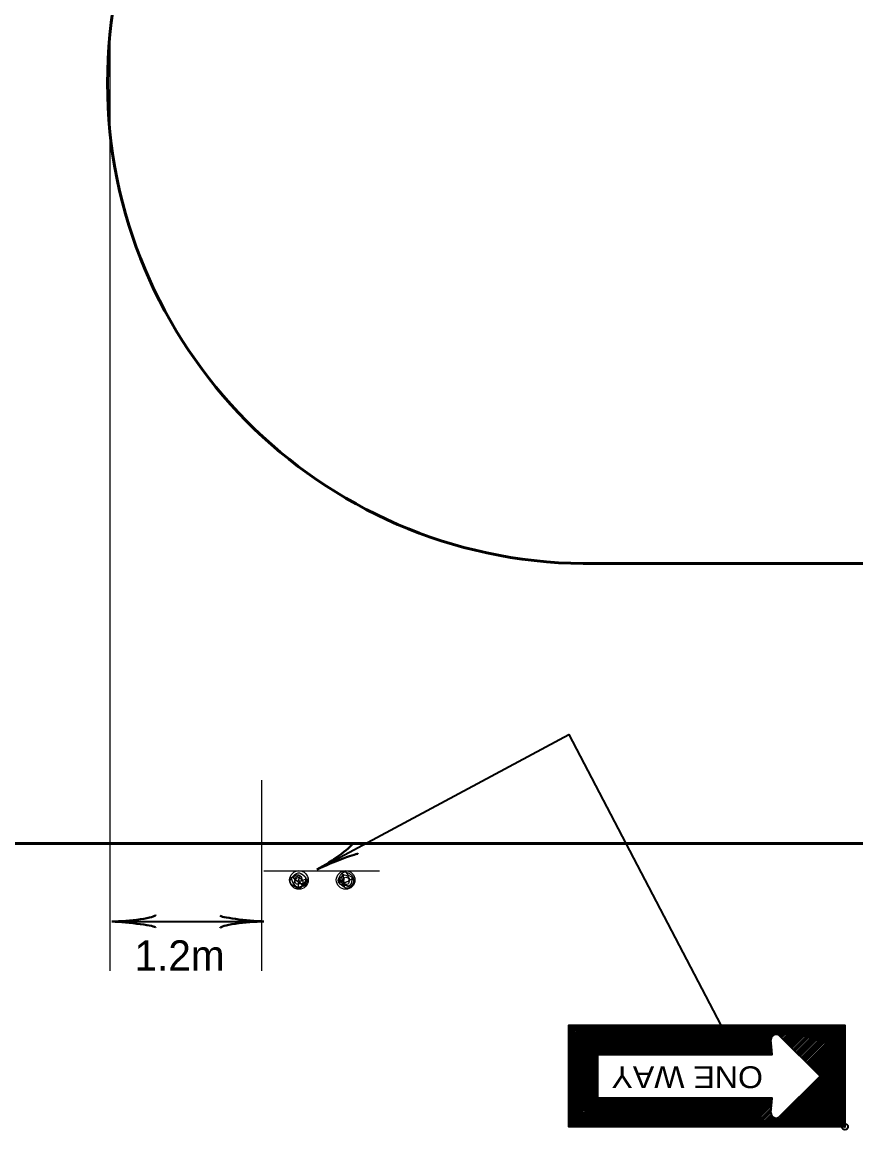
# Model space of a CAD drawing. Extents: x -198 to 658, y -402 to 142.
# Drawn here: x 64.2 to 130.3, y -164.9 to -77.1 of the extents above; entities that cross this region are included whole.
import ezdxf
from ezdxf.enums import TextEntityAlignment as Align

# ---------------------------------------------------------------- set-up
doc = ezdxf.new("R2010")
doc.units = 0
doc.header["$LTSCALE"] = 0.96
doc.header["$PDMODE"] = 32
doc.header["$PDSIZE"] = 0.48
doc.layers.add('1', color=7, linetype='Continuous', lineweight=35)
doc.layers.add('4', color=7, linetype='Continuous', lineweight=25)

msp = doc.modelspace()

# ---------------------------------------------------------------- linework, layer by layer
at = {"layer": '1', "lineweight": 25}
for p, q in [((71.1619, -152.3203), (71.1619, -77.8663)), ((83.1828, -152.3203), (83.1828, -137.1946)), ((92.5121, -144.4125), (83.3321, -144.4125))]:
    msp.add_line(p, q, dxfattribs=at)
at = {"layer": '1', "lineweight": 53}
for p, q in [((234.6408, -120.0238), (108.6408, -120.0238)), ((-105.2517, -142.2238), (234.6408, -142.2238))]:
    msp.add_line(p, q, dxfattribs=at)
at = {"layer": '1'}
for p, q in [((71.3032, -148.4168), (83.3241, -148.4168)), ((112.0494, -156.6375), (107.5134, -161.1735)), ((111.8814, -156.6375), (107.5134, -161.0055)), ((111.7134, -156.6375), (107.5134, -160.8375)), ((111.5694, -156.6375), (107.5134, -160.6695)), ((111.4014, -156.6375), (107.5134, -160.5255)), ((111.2334, -156.6375), (107.5134, -160.3575)), ((111.0654, -156.6375), (107.5134, -160.1895)), ((110.9214, -156.6375), (107.5134, -160.0215)), ((110.7534, -156.6375), (107.5134, -159.8535)), ((110.5854, -156.6375), (107.5134, -159.7095)), ((110.4174, -156.6375), (107.5134, -159.5415)), ((110.2494, -156.6375), (107.5134, -159.3735)), ((110.1054, -156.6375), (107.5134, -159.2055)), ((109.9374, -156.6375), (107.5134, -159.0375)), ((109.7694, -156.6375), (107.5134, -158.8935)), ((109.6014, -156.6375), (107.5134, -158.7255)), ((109.4334, -156.6375), (107.5134, -158.5575)), ((109.2894, -156.6375), (107.5134, -158.3895)), ((109.1214, -156.6375), (107.5134, -158.2455)), ((108.9534, -156.6375), (107.5134, -158.0775)), ((108.7854, -156.6375), (107.5134, -157.9095)), ((108.6414, -156.6375), (107.5134, -157.7415)), ((108.4734, -156.6375), (107.5134, -157.5735)), ((108.3054, -156.6375), (107.5134, -157.4295)), ((108.1374, -156.6375), (107.5134, -157.2615)), ((107.9694, -156.6375), (107.5134, -157.0935)), ((107.8254, -156.6375), (107.5134, -156.9255)), ((107.6574, -156.6375), (107.5134, -156.7575)), ((112.2174, -156.6375), (109.8894, -158.9655)), ((112.3854, -156.6375), (110.0574, -158.9655)), ((112.5294, -156.6375), (110.2254, -158.9655)), ((112.6974, -156.6375), (110.3694, -158.9655)), ((112.8654, -156.6375), (110.5374, -158.9655)), ((113.0334, -156.6375), (110.7054, -158.9655)), ((113.2014, -156.6375), (110.8734, -158.9655)), ((113.3454, -156.6375), (111.0174, -158.9655)), ((113.5134, -156.6375), (111.1854, -158.9655)), ((113.6814, -156.6375), (111.3534, -158.9655)), ((113.8494, -156.6375), (111.5214, -158.9655)), ((114.0174, -156.6375), (111.6894, -158.9655)), ((114.1614, -156.6375), (111.8334, -158.9655)), ((114.3294, -156.6375), (112.0014, -158.9655)), ((114.4974, -156.6375), (112.1694, -158.9655)), ((114.6654, -156.6375), (112.3374, -158.9655)), ((114.8094, -156.6375), (112.5054, -158.9655)), ((114.9774, -156.6375), (112.6494, -158.9655)), ((115.1454, -156.6375), (112.8174, -158.9655)), ((115.3134, -156.6375), (112.9854, -158.9655)), ((115.4814, -156.6375), (113.1534, -158.9655)), ((115.6254, -156.6375), (113.3214, -158.9655)), ((115.7934, -156.6375), (113.4654, -158.9655)), ((115.9614, -156.6375), (113.6334, -158.9655)), ((116.1294, -156.6375), (113.8014, -158.9655)), ((116.2974, -156.6375), (113.9694, -158.9655)), ((116.4414, -156.6375), (114.1134, -158.9655)), ((116.6094, -156.6375), (114.2814, -158.9655)), ((116.7774, -156.6375), (114.4494, -158.9655)), ((116.9454, -156.6375), (114.6174, -158.9655)), ((117.0894, -156.6375), (114.7854, -158.9655)), ((117.2574, -156.6375), (114.9294, -158.9655)), ((117.4254, -156.6375), (115.0974, -158.9655)), ((117.5934, -156.6375), (115.2654, -158.9655)), ((117.7614, -156.6375), (115.4334, -158.9655)), ((117.9054, -156.6375), (115.6014, -158.9655)), ((118.0734, -156.6375), (115.7454, -158.9655)), ((118.2414, -156.6375), (115.9134, -158.9655)), ((118.4094, -156.6375), (116.0814, -158.9655)), ((118.5774, -156.6375), (116.2494, -158.9655)), ((118.7214, -156.6375), (116.3934, -158.9655)), ((118.8894, -156.6375), (116.5614, -158.9655)), ((119.0574, -156.6375), (116.7294, -158.9655)), ((119.2254, -156.6375), (116.8974, -158.9655)), ((119.3934, -156.6375), (117.0654, -158.9655)), ((119.5374, -156.6375), (117.2094, -158.9655)), ((119.7054, -156.6375), (117.3774, -158.9655)), ((119.8734, -156.6375), (117.5454, -158.9655)), ((120.0414, -156.6375), (117.7134, -158.9655)), ((120.1854, -156.6375), (117.8814, -158.9655)), ((120.3534, -156.6375), (118.0254, -158.9655)), ((120.5214, -156.6375), (118.1934, -158.9655)), ((120.6894, -156.6375), (118.3614, -158.9655)), ((120.8574, -156.6375), (118.5294, -158.9655)), ((121.0014, -156.6375), (118.6974, -158.9655)), ((121.1694, -156.6375), (118.8414, -158.9655)), ((121.3374, -156.6375), (119.0094, -158.9655)), ((121.5054, -156.6375), (119.1774, -158.9655)), ((121.6734, -156.6375), (119.3454, -158.9655)), ((121.8174, -156.6375), (119.4894, -158.9655)), ((121.9854, -156.6375), (119.6574, -158.9655)), ((122.1534, -156.6375), (119.8254, -158.9655)), ((122.3214, -156.6375), (119.9934, -158.9655)), ((122.4894, -156.6375), (120.1614, -158.9655)), ((122.6334, -156.6375), (120.3054, -158.9655)), ((122.8014, -156.6375), (120.4734, -158.9655)), ((122.9694, -156.6375), (120.6414, -158.9655)), ((123.1374, -156.6375), (120.8094, -158.9655)), ((123.2814, -156.6375), (120.9774, -158.9655)), ((123.4494, -156.6375), (121.1214, -158.9655)), ((123.6174, -156.6375), (121.2894, -158.9655)), ((123.7854, -156.6375), (121.4574, -158.9655)), ((123.9534, -156.6375), (121.6254, -158.9655)), ((124.0974, -156.6375), (121.7934, -158.9655)), ((124.2654, -156.6375), (121.9374, -158.9655)), ((124.4334, -156.6375), (122.1054, -158.9655)), ((124.6014, -156.6375), (123.8574, -157.3815)), ((124.7694, -156.6375), (124.0254, -157.3815)), ((124.9134, -156.6375), (124.1454, -157.4055)), ((125.0814, -156.6375), (124.2174, -157.4775)), ((125.2494, -156.6375), (124.3134, -157.5735)), ((125.4174, -156.6375), (124.3854, -157.6455)), ((125.5614, -156.6375), (124.4814, -157.7415)), ((125.7294, -156.6375), (124.5534, -157.8135)), ((125.8974, -156.6375), (124.6254, -157.8855)), ((126.0654, -156.6375), (124.7214, -157.9815)), ((126.2334, -156.6375), (124.7934, -158.0535)), ((126.3774, -156.6375), (124.8894, -158.1495)), ((126.5454, -156.6375), (124.9614, -158.2215)), ((126.7134, -156.6375), (125.0334, -158.2935)), ((126.8814, -156.6375), (125.1294, -158.3895)), ((127.0494, -156.6375), (125.2014, -158.4615)), ((127.1934, -156.6375), (125.2974, -158.5575)), ((127.3614, -156.6375), (125.3694, -158.6295)), ((127.5294, -156.6375), (125.4414, -158.7015)), ((127.6974, -156.6375), (125.5374, -158.7975)), ((127.8654, -156.6375), (125.6094, -158.8695)), ((128.0094, -156.6375), (125.7054, -158.9655)), ((128.1774, -156.6375), (125.7774, -159.0375)), ((128.3454, -156.6375), (125.8494, -159.1095)), ((128.5134, -156.6375), (125.9454, -159.2055)), ((128.6574, -156.6375), (126.0174, -159.2775)), ((128.8254, -156.6375), (126.1134, -159.3495)), ((128.9934, -156.6375), (126.1854, -159.4455)), ((129.1614, -156.6375), (126.2574, -159.5175)), ((129.3294, -156.6375), (126.3534, -159.6135)), ((129.4014, -156.7095), (126.4254, -159.6855)), ((129.4014, -156.8775), (126.5214, -159.7575)), ((129.4014, -157.0455), (126.5934, -159.8535)), ((129.4014, -157.1895), (126.6654, -159.9255)), ((123.5454, -157.6935), (122.2734, -158.9655)), ((123.5454, -157.8615), (122.4414, -158.9655)), ((123.5454, -158.0055), (122.5854, -158.9655)), ((123.5694, -158.1495), (122.7534, -158.9655)), ((124.1694, -157.4295), (127.4334, -160.6935)), ((129.4014, -157.3575), (126.7614, -160.0215)), ((129.4014, -157.5255), (126.8334, -160.0935)), ((129.4014, -157.6935), (126.9054, -160.1655)), ((129.4014, -157.8615), (127.0014, -160.2615)), ((129.4014, -158.0055), (127.0734, -160.3335)), ((123.5694, -158.2935), (122.9214, -158.9655)), ((123.5934, -158.4615), (123.0894, -158.9655)), ((123.5934, -158.6055), (123.2574, -158.9655)), ((123.6174, -158.7495), (123.4014, -158.9655)), ((129.4014, -158.8215), (123.5454, -164.7015)), ((123.6174, -158.8935), (123.5694, -158.9655)), ((129.4014, -158.9895), (123.6894, -164.7015)), ((129.4014, -158.1735), (127.1694, -160.4295)), ((129.4014, -158.3415), (127.2414, -160.5015)), ((129.4014, -158.5095), (127.3134, -160.5735)), ((129.4014, -158.6775), (127.4094, -160.6695)), ((109.8174, -159.0375), (107.5134, -161.3415)), ((109.8174, -159.2055), (107.5134, -161.4855)), ((109.8174, -159.3735), (107.5134, -161.6535)), ((109.8174, -159.5175), (107.5134, -161.8215)), ((109.8174, -159.6855), (107.5134, -161.9895)), ((109.8174, -159.8535), (107.5134, -162.1335)), ((129.4014, -159.1575), (123.8574, -164.7015)), ((129.4014, -159.3255), (124.0254, -164.7015)), ((129.4014, -159.4695), (124.1934, -164.7015)), ((129.4014, -159.6375), (124.3614, -164.7015)), ((129.4014, -159.8055), (124.5054, -164.7015)), ((109.8174, -160.0215), (107.5134, -162.3015)), ((109.8174, -160.1655), (107.5134, -162.4695)), ((109.8174, -160.3335), (107.5134, -162.6375)), ((109.8174, -160.5015), (107.5134, -162.8055)), ((109.8174, -160.6695), (107.5134, -162.9495)), ((127.4334, -160.6935), (124.1694, -163.9335)), ((129.4014, -159.9735), (124.6734, -164.7015)), ((129.4014, -160.1415), (124.8414, -164.7015)), ((129.4014, -160.2855), (125.0094, -164.7015)), ((129.4014, -160.4535), (125.1774, -164.7015)), ((129.4014, -160.6215), (125.3214, -164.7015)), ((109.8174, -160.8375), (107.5134, -163.1175)), ((109.8174, -160.9815), (107.5134, -163.2855)), ((109.8174, -161.1495), (107.5134, -163.4535)), ((109.8174, -161.3175), (107.5134, -163.6215)), ((109.8174, -161.4855), (107.5134, -163.7655)), ((109.8174, -161.6535), (107.5134, -163.9335)), ((129.4014, -160.7895), (125.4894, -164.7015)), ((129.4014, -160.9575), (125.6574, -164.7015)), ((129.4014, -161.1015), (125.8254, -164.7015)), ((129.4014, -161.2695), (125.9694, -164.7015)), ((129.4014, -161.4375), (126.1374, -164.7015)), ((129.4014, -161.6055), (126.3054, -164.7015)), ((109.8174, -161.7975), (107.5134, -164.1015)), ((109.8174, -161.9655), (107.5134, -164.2695)), ((109.8174, -162.1335), (107.5134, -164.4375)), ((109.8174, -162.3015), (107.5134, -164.5815)), ((109.8654, -162.4215), (107.5614, -164.7015)), ((110.0094, -162.4215), (107.7294, -164.7015)), ((110.1774, -162.4215), (107.8974, -164.7015)), ((110.3454, -162.4215), (108.0654, -164.7015)), ((110.5134, -162.4215), (108.2334, -164.7015)), ((110.6574, -162.4215), (108.3774, -164.7015)), ((110.8254, -162.4215), (108.5454, -164.7015)), ((110.9934, -162.4215), (108.7134, -164.7015)), ((111.1614, -162.4215), (108.8814, -164.7015)), ((111.3294, -162.4215), (109.0254, -164.7015)), ((111.4734, -162.4215), (109.1934, -164.7015)), ((111.6414, -162.4215), (109.3614, -164.7015)), ((111.8094, -162.4215), (109.5294, -164.7015)), ((111.9774, -162.4215), (109.6974, -164.7015)), ((112.1454, -162.4215), (109.8414, -164.7015)), ((112.2894, -162.4215), (110.0094, -164.7015)), ((112.4574, -162.4215), (110.1774, -164.7015)), ((112.6254, -162.4215), (110.3454, -164.7015)), ((112.7934, -162.4215), (110.5134, -164.7015)), ((112.9374, -162.4215), (110.6574, -164.7015)), ((113.1054, -162.4215), (110.8254, -164.7015)), ((113.2734, -162.4215), (110.9934, -164.7015)), ((113.4414, -162.4215), (111.1614, -164.7015)), ((113.6094, -162.4215), (111.3294, -164.7015)), ((113.7534, -162.4215), (111.4734, -164.7015)), ((113.9214, -162.4215), (111.6414, -164.7015)), ((114.0894, -162.4215), (111.8094, -164.7015)), ((114.2574, -162.4215), (111.9774, -164.7015)), ((114.4254, -162.4215), (112.1214, -164.7015)), ((114.5694, -162.4215), (112.2894, -164.7015)), ((114.7374, -162.4215), (112.4574, -164.7015)), ((114.9054, -162.4215), (112.6254, -164.7015)), ((115.0734, -162.4215), (112.7934, -164.7015)), ((115.2414, -162.4215), (112.9374, -164.7015)), ((115.3854, -162.4215), (113.1054, -164.7015)), ((115.5534, -162.4215), (113.2734, -164.7015)), ((115.7214, -162.4215), (113.4414, -164.7015)), ((115.8894, -162.4215), (113.6094, -164.7015)), ((116.0334, -162.4215), (113.7534, -164.7015)), ((116.2014, -162.4215), (113.9214, -164.7015)), ((116.3694, -162.4215), (114.0894, -164.7015)), ((116.5374, -162.4215), (114.2574, -164.7015)), ((116.7054, -162.4215), (114.4254, -164.7015)), ((116.8494, -162.4215), (114.5694, -164.7015)), ((117.0174, -162.4215), (114.7374, -164.7015)), ((117.1854, -162.4215), (114.9054, -164.7015)), ((117.3534, -162.4215), (115.0734, -164.7015)), ((117.5214, -162.4215), (115.2174, -164.7015)), ((117.6654, -162.4215), (115.3854, -164.7015)), ((117.8334, -162.4215), (115.5534, -164.7015)), ((118.0014, -162.4215), (115.7214, -164.7015)), ((118.1694, -162.4215), (115.8894, -164.7015)), ((118.3374, -162.4215), (116.0334, -164.7015)), ((118.4814, -162.4215), (116.2014, -164.7015)), ((118.6494, -162.4215), (116.3694, -164.7015)), ((118.8174, -162.4215), (116.5374, -164.7015)), ((118.9854, -162.4215), (116.7054, -164.7015)), ((119.1294, -162.4215), (116.8494, -164.7015)), ((119.2974, -162.4215), (117.0174, -164.7015)), ((119.4654, -162.4215), (117.1854, -164.7015)), ((119.6334, -162.4215), (117.3534, -164.7015)), ((119.8014, -162.4215), (117.4974, -164.7015)), ((119.9454, -162.4215), (117.6654, -164.7015)), ((120.1134, -162.4215), (117.8334, -164.7015)), ((120.2814, -162.4215), (118.0014, -164.7015)), ((120.4494, -162.4215), (118.1694, -164.7015)), ((120.6174, -162.4215), (118.3134, -164.7015)), ((120.7614, -162.4215), (118.4814, -164.7015)), ((120.9294, -162.4215), (118.6494, -164.7015)), ((121.0974, -162.4215), (118.8174, -164.7015)), ((121.2654, -162.4215), (118.9854, -164.7015)), ((121.4094, -162.4215), (119.1294, -164.7015)), ((121.5774, -162.4215), (119.2974, -164.7015)), ((121.7454, -162.4215), (119.4654, -164.7015)), ((121.9134, -162.4215), (119.6334, -164.7015)), ((122.0814, -162.4215), (119.8014, -164.7015)), ((122.2254, -162.4215), (119.9454, -164.7015)), ((122.3934, -162.4215), (120.1134, -164.7015)), ((122.5614, -162.4215), (120.2814, -164.7015)), ((122.7294, -162.4215), (120.4494, -164.7015)), ((122.8974, -162.4215), (120.5934, -164.7015)), ((123.0414, -162.4215), (120.7614, -164.7015)), ((123.2094, -162.4215), (120.9294, -164.7015)), ((123.3774, -162.4215), (121.0974, -164.7015)), ((123.5454, -162.4215), (121.2654, -164.7015)), ((123.6174, -162.4935), (121.4094, -164.7015)), ((129.4014, -161.7735), (126.4734, -164.7015)), ((129.4014, -161.9175), (126.6414, -164.7015)), ((129.4014, -162.0855), (126.7854, -164.7015)), ((129.4014, -162.2535), (126.9534, -164.7015)), ((129.4014, -162.4215), (127.1214, -164.7015)), ((123.6174, -162.6615), (121.5774, -164.7015)), ((123.5934, -162.8535), (121.7454, -164.7015)), ((123.5694, -163.0215), (121.9134, -164.7015)), ((123.5694, -163.2135), (122.0814, -164.7015)), ((123.5454, -163.3815), (122.2254, -164.7015)), ((129.4014, -162.5655), (127.2894, -164.7015)), ((129.4014, -162.7335), (127.4574, -164.7015)), ((129.4014, -162.9015), (127.6014, -164.7015)), ((129.4014, -163.0695), (127.7694, -164.7015)), ((129.4014, -163.2375), (127.9374, -164.7015)), ((129.4014, -163.3815), (128.1054, -164.7015)), ((123.5214, -163.5495), (122.3934, -164.7015)), ((123.5454, -163.7175), (122.5614, -164.7015)), ((123.5934, -163.8135), (122.7294, -164.7015)), ((123.6894, -163.9095), (122.8734, -164.7015)), ((123.7854, -163.9575), (123.0414, -164.7015)), ((123.9054, -164.0055), (123.2094, -164.7015)), ((124.0974, -163.9815), (123.3774, -164.7015)), ((129.4014, -163.5495), (128.2734, -164.7015)), ((129.4014, -163.7175), (128.4174, -164.7015)), ((129.4014, -163.8855), (128.5854, -164.7015)), ((129.4014, -164.0535), (128.7534, -164.7015)), ((129.4014, -164.1975), (128.9214, -164.7015)), ((129.4014, -164.3655), (129.0654, -164.7015)), ((129.4014, -164.5335), (129.2334, -164.7015))]:
    msp.add_line(p, q, dxfattribs=at)
for points in [[(87.5611, -144.2849), (107.5263, -133.5857), (119.5534, -156.6375)], [(123.5214, -163.5495), (123.6414, -162.4215), (109.8174, -162.4215), (109.8174, -158.9655), (123.6414, -158.9655), (123.5214, -157.8135)]]:
    msp.add_lwpolyline(points, dxfattribs=at)
msp.add_lwpolyline([(129.4014, -164.7015), (107.5134, -164.7015), (107.5134, -156.6375), (129.4014, -156.6375)], close=True, dxfattribs=at)
at = {"layer": '1', "lineweight": 53}
msp.add_arc((109.0474, -81.9238), 38.1022, 90.61145, 269.38854, dxfattribs=at)
at = {"layer": '1'}
for centre, start, end in [((123.9506, -157.7848), 58.76645, 183.36449), ((123.9506, -163.5851), 176.63551, 301.23355)]:
    msp.add_arc(centre, 0.419, start, end, dxfattribs=at)
at = {"layer": '1', "lineweight": 40}
for centre, major_axis, ratio, start_param, end_param in [((88.5587, -143.3742), (-1.8002, -1.1773), 0.122415, 0.8963533, 3.1415927), ((88.8662, -143.8736), (-1.9574, -0.8098), 0.07063, 3.1407148, 5.41811), ((72.6478, -148.6707), (-2.1077, 0.2108), 0.07063, 3.1407148, 5.41811), ((72.6126, -148.0852), (-2.1428, -0.1874), 0.122415, 0.8963533, 3.1415927), ((82.0147, -148.7484), (2.1428, 0.1874), 0.122415, 0.8963533, 3.1415927), ((81.9795, -148.1629), (2.1077, -0.2108), 0.07063, 3.1407148, 5.41811)]:
    msp.add_ellipse(centre, major_axis=major_axis, ratio=ratio, start_param=start_param, end_param=end_param, dxfattribs=at)
at = {"layer": '1', "lineweight": 25}
for points in [[(86.1761, -144.5565), (86.5361, -144.8085), (86.7161, -145.1685), (86.6081, -145.4205), (86.2121, -145.6725), (85.8161, -145.6725), (85.4201, -145.2765), (85.6721, -144.8085), (86.1761, -144.5565), (86.3921, -144.7005), (86.5721, -144.8085), (86.6441, -145.1325), (86.3921, -145.5645), (86.2481, -145.7445), (85.7441, -145.4565), (85.8161, -145.0965), (85.8881, -144.8805), (86.0321, -144.8085), (86.2481, -144.8085), (86.3561, -145.0245), (86.3921, -145.4205), (86.1401, -145.4205), (85.9601, -145.4565), (85.8161, -145.2405), (86.0681, -144.9165), (86.2841, -145.0605), (86.3201, -145.2045), (86.0681, -145.2405), (86.1041, -145.3125), (85.5641, -144.9165), (86.0321, -145.7805), (86.1401, -145.2765), (86.4641, -145.6005), (86.8241, -145.0965), (86.0681, -145.2405), (86.2121, -144.7725), (85.7081, -144.8805), (86.0681, -145.2405)], [(89.8121, -144.4845), (90.2081, -144.6645), (90.4601, -145.0605), (90.3881, -145.4925), (89.9201, -145.7805), (89.4881, -145.5285), (89.2361, -145.1685), (89.3081, -144.9165), (89.8121, -144.4845), (90.0641, -144.7725), (90.2801, -144.8805), (90.3161, -145.0965), (90.0641, -145.6005), (89.8121, -145.5645), (89.6321, -145.4205), (89.3441, -145.2405), (89.5601, -144.8085), (89.8481, -144.7365), (90.0281, -144.8805), (90.1361, -145.0965), (90.0641, -145.3125), (89.9921, -145.4565), (89.6321, -145.3485), (89.7041, -145.0965), (89.7041, -144.9525), (89.9921, -144.9525), (90.0641, -145.1685), (89.6681, -145.3125), (89.5961, -145.2765), (89.2721, -144.9525), (89.7401, -145.6365), (89.6321, -145.3125), (90.1721, -145.6725), (90.4241, -145.0605), (89.6681, -145.3125), (89.6321, -144.6645), (89.5241, -144.8085), (89.6681, -145.3125)]]:
    msp.add_spline(points, degree=3, dxfattribs=at)
at = {"layer": '1'}
msp.add_point((129.4014, -164.7015), dxfattribs=at)
at = {"layer": '4'}
for centre in [(86.1183, -145.121), (89.8205, -145.1207)]:
    msp.add_circle(centre, 0.738, dxfattribs=at)

# ---------------------------------------------------------------- texts
at = {"layer": '1'}
msp.add_text('1.2m', height=2.4, dxfattribs=at).set_placement((76.6597, -152.3109), align=Align.CENTER)
at = {"layer": '1', "width": 1.1}
msp.add_text('ONE WAY', height=1.728, rotation=180, dxfattribs=at).set_placement((116.897, -159.9015), align=Align.CENTER)

doc.saveas('drawing.dxf')
